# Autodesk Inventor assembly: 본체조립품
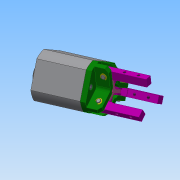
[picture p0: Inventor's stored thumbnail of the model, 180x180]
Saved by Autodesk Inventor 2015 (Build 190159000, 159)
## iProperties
Created: 2020-02
Part Number: 본체조립품
Document SubType Name: Assembly
Designer: user
Author: user
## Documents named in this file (13)
- C:\Users\user\Desktop\700206V1006\본체조립품.iam
- C:\Users\user\Desktop\700206V1006\로드.ipt
- C:\Users\user\Desktop\700206V1006\피스톤.ipt
- C:\Users\user\Desktop\700206V1006\O-RING 12x16.ipt
- C:\Users\user\Desktop\700206V1006\O-RING 34x40.ipt
- C:\Users\user\Desktop\700206V1006\본체.ipt
- C:\Users\user\Desktop\700206V1006\본체헤드.ipt
- C:\Users\user\Desktop\700206V1006\O-RING 18x22.ipt
- C:\Users\user\Desktop\700206V1006\핑거.ipt
- C:\Users\user\Desktop\700206V1006\핀 B.ipt
- C:\Users\user\Desktop\700206V1006\핀 A.ipt
- C:\Users\user\Desktop\700206V1006\E링.ipt
- C:\Users\user\Desktop\700206V1006\볼트 M4.ipt
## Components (20 placed, 8 different names)
1. 피스톤:1
2. O-RING 12x16:1
3. O-RING 34x40:1
4. O-RING 34x40:2
5. O-RING 18x22:1
6. 핑거:1
7. 핑거:2
8. 핑거:3
9. 핀 B:1
10. 핀 B:2
11. 핀 B:3
12. E링:1
13. E링:2
14. E링:3
15. E링:4
16. E링:5
17. E링:6
18. 핀 A:1
19. 핀 A:2
20. 핀 A:3
